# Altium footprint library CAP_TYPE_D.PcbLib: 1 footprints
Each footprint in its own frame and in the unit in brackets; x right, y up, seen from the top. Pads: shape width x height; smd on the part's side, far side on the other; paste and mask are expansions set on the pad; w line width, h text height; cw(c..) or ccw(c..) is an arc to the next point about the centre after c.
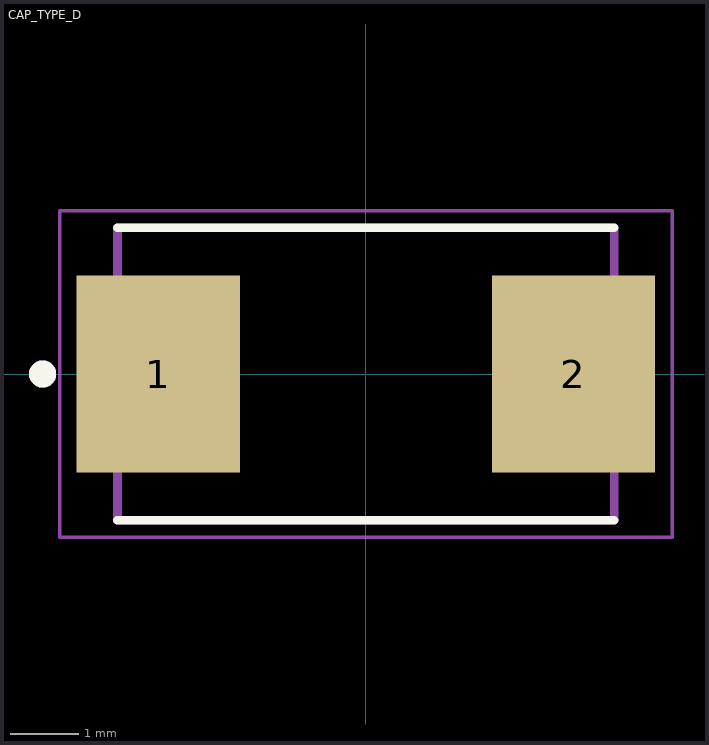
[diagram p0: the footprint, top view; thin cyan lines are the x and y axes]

## CAP_TYPE_D [mm]
pads (2):
  rect 2.4x2.9 smd: 1(-3.05,0) 2(3.05,0)
Top Overlay:
  circle w0.2: c-4.75,0 r0.1
  lines w0.127: -3.65,-2.15 3.65,-2.15 ; -3.65,2.15 3.65,2.15
Mechanical 13:
  circle w0.2: c-4.75,0 r0.1
  lines w0.127: -3.65,-2.15 -3.65,2.15 3.65,2.15 3.65,-2.15 -3.65,-2.15
Mechanical 15:
  lines w0.05: -4.5,-2.4 -4.5,2.4 4.5,2.4 4.5,-2.4 -4.5,-2.4
3D body "CAP_TYPE_D.STEP": height 3.1, standoff 0, extent -3.65,-2.268 3.65,2.032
